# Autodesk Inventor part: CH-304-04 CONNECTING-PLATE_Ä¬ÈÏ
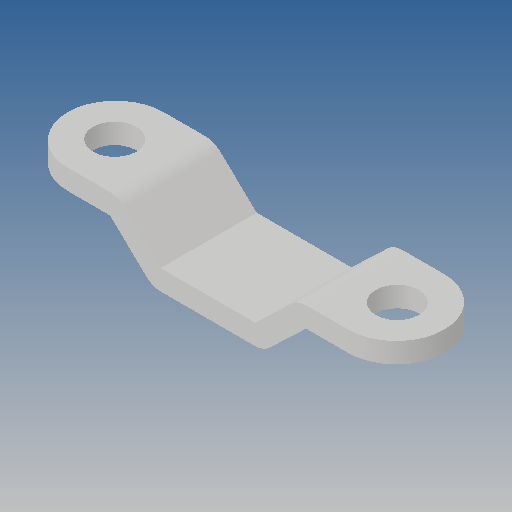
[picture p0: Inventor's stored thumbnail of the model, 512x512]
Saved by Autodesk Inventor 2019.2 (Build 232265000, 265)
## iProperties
Created: 2010-06
Part Number: CH-304-04 CONNECTING-PLATE_Ä¬ÈÏ
Material: Ogólny
Document SubType Name: Modeling
Designer: CADENGINEERING4
Density: 1 g/cm^3
Appearance: Domyślna
Author: CADENGINEERING4
Revision Number: ÈÎºÎ
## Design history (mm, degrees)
feature "NONE"
node "Bryła1"
